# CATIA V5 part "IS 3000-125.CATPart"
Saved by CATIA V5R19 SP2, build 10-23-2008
Part number: IS 3000-125
Bounding box of the stored display mesh (mm): x -47.487 to 47.487, y -47.487 to 47.487, z 0 to 370
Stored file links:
  C:\Users\Bora\Desktop\3D Katı model\IS serisi\IS 3000\IS 3000-125.CATPart
  C:\Program Files\Dassault Systemes\B19\intel_a\reffiles\standard\MetricThickPitch.txt
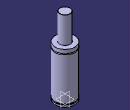
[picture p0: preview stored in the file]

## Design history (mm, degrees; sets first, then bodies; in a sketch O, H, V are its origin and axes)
Body1 (main body)
  Sketch1 on yz-plane, origin (0, 0, 0), H (0, 1, 0), V (0, 0, 1)
    point P1 (47.5, 223.5)
    point P2 (47.5, 218.5)
    point P5 (25, 369)
    point P7 (25, 369)
    point P12 (47.5, 218.5)
    point P13 (47.5, 223.5)
    arc A1 centre (47.5, 221) radius 2.5 from (47.5, 223.5) to (47.5, 218.5) ccw
    line L1 (47.5, 0) -> (47.5, 8)
    line L2 (25, 369) -> (25, 242)
    arc A2 centre (24, 369) radius 1 from (25, 369) to (24, 370) ccw
    line L3 (43.5, 13) -> (43.5, 8)
    line L4 (47.5, 13) -> (47.5, 218.5)
    line L5 (47.5, 223.5) -> (47.5, 242)
    line L6 (24, 370) -> (0, 370)
    point P15 (0, 370)
    line L7 (25, 242) -> (47.5, 242)
    line L8 (0, 0) -> (47.5, 0)
    line L9 (43.5, 13) -> (47.5, 13)
    line L10 (43.5, 8) -> (47.5, 8)
    coincidence: P15 V, P1 P13, P2 P12, P5 P7
    tangency: L6 A2
    horizontal: L7 H, L8 H, L9 H, L10 H
  Shaft1: profile Sketch1, axis Sketch1.V, angle 360
  Sketch2 on face of Shaft1 from Sketch1.L8, origin (0, 0, 0), H (1, 0, 0), V (0, -1, 0)
    point P1 (30, 0)
    distance P1 V = 30
  Hole1: placed by Sketch2, at (30, 0, 0) direction (0, 0, 1), diameter 6.647, depth 13, threaded "M8", thread diameter 8, thread depth 13, pitch 1.25
  CircPattern1: of Hole1, instances 4, angular step 90, axis from face of Shaft1 from Sketch1.L8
